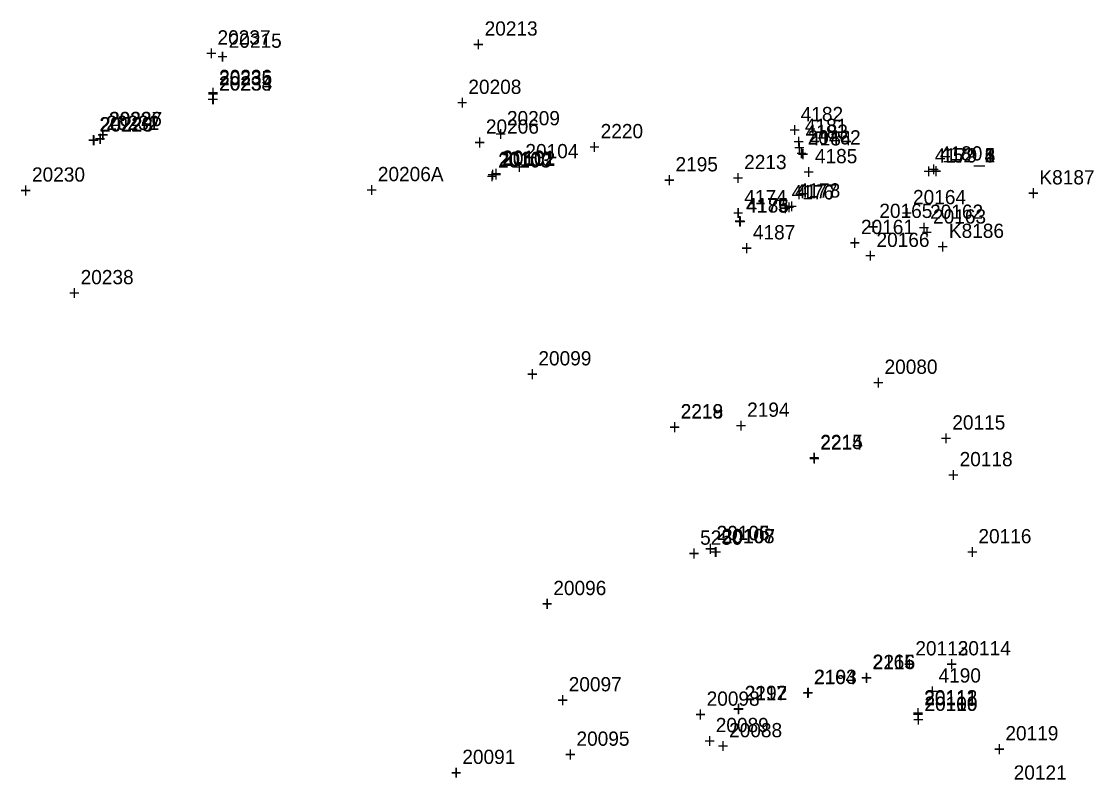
# Model space of a CAD drawing. Extents: x 1036751 to 1042192, y 772604 to 785439.
# Drawn here: x 1041373 to 1041558.5, y 774481.9 to 774615 of the extents above; entities that cross this region are included whole.
import ezdxf

# ---------------------------------------------------------------- set-up
doc = ezdxf.new("R2010")
doc.units = 0
for name, color, linetype in [('S_Annotation_Label', 7, 'Continuous'), ('S_Buildings', 7, 'Continuous'), ('S_Buildings_SillElevation', 7, 'Continuous'), ('S_Control_Temp_Traverse', 7, 'Continuous'), ('S_Curb_Type_2', 7, 'Continuous'), ('S_Drainage_CB', 7, 'Continuous'), ('S_Drainage_Culvert_Top', 7, 'Continuous'), ('S_Drainage_Invert', 7, 'Continuous'), ('S_Drainage_Sump', 7, 'Continuous'), ('S_Property_IronPipeFound', 7, 'Continuous'), ('S_Property_Lawn', 7, 'Continuous'), ('S_Roadway_Centerline', 7, 'Continuous'), ('S_Roadway_Edge_Pavement', 7, 'Continuous'), ('S_Roadway_Edge_TW', 7, 'Continuous'), ('S_Traffic_Sign_DoublePost', 7, 'Continuous'), ('S_Traffic_Sign_SinglePost', 7, 'Continuous'), ('S_Trees_Conifer_Pay', 7, 'Continuous'), ('S_Utilities_GuyWire3', 7, 'Continuous'), ('S_Utilities_Hydrant', 7, 'Continuous'), ('S_Utilities_Pole_Power', 7, 'Continuous'), ('S_Utilities_UG_Sanitary_MH', 7, 'Continuous'), ('S_Utilities_UG_Sanitary_Sewer', 7, 'Continuous'), ('S_Utilities_UG_Water_Gate', 7, 'Continuous'), ('S_Utilities_UG_Water_Line', 7, 'Continuous'), ('S_Utilities_UG_Water_Shutoff', 7, 'Continuous')]:
    doc.layers.add(name, color=color, linetype=linetype)

msp = doc.modelspace()

# ---------------------------------------------------------------- texts
at = {"layer": 'S_Annotation_Label'}
for s, p in [('20213', (1041454.27, 774612.43)), ('+', (1041452.21, 774609.68))]:
    msp.add_text(s, height=2.5, dxfattribs=at).set_placement(p)
at = {"layer": 'S_Buildings'}
for s, p in [('20206', (1041454.49, 774595.24)), ('+', (1041452.43, 774592.49)), ('20206A', (1041435.54, 774586.91)), ('+', (1041433.48, 774584.16)), ('20115', (1041536.3, 774543.36)), ('+', (1041534.23, 774540.61)), ('20116', (1041540.88, 774523.42)), ('+', (1041538.82, 774520.67)), ('20096', (1041466.32, 774514.34)), ('+', (1041464.26, 774511.59)), ('20119', (1041545.61, 774488.87)), ('20095', (1041470.38, 774487.92)), ('20091', (1041450.36, 774484.73)), ('+', (1041468.32, 774485.17)), ('+', (1041543.55, 774486.12)), ('+', (1041448.3, 774481.98))]:
    msp.add_text(s, height=2.5, dxfattribs=at).set_placement(p)
at = {"layer": 'S_Buildings_SillElevation'}
for s, p in [('20208', (1041451.42, 774602.21)), ('+', (1041449.36, 774599.46)), ('20118', (1041537.58, 774536.93)), ('+', (1041535.52, 774534.18)), ('20097', (1041469.02, 774497.46)), ('+', (1041466.96, 774494.71)), ('20121', (1041547.06, 774481.98))]:
    msp.add_text(s, height=2.5, dxfattribs=at).set_placement(p)
at = {"layer": 'S_Control_Temp_Traverse'}
for s, p in [('152', (1041534.53, 774590.2)), ('152', (1041534.53, 774590.2)), ('152_1', (1041534.53, 774590.2)), ('152_3', (1041534.53, 774590.2)), ('152_2', (1041534.53, 774590.2)), ('152_5', (1041534.53, 774590.2)), ('152_4', (1041534.53, 774590.2)), ('152_6', (1041534.53, 774590.2)), ('+', (1041532.47, 774587.45)), ('+', (1041532.47, 774587.45)), ('+', (1041532.47, 774587.45)), ('+', (1041532.47, 774587.45)), ('+', (1041532.47, 774587.45)), ('+', (1041532.47, 774587.45)), ('+', (1041532.47, 774587.45)), ('+', (1041532.47, 774587.45))]:
    msp.add_text(s, height=2.5, dxfattribs=at).set_placement(p)
at = {"layer": 'S_Curb_Type_2'}
for s, p in [('5250', (1041492.06, 774523.17)), ('+', (1041490, 774520.42))]:
    msp.add_text(s, height=2.5, dxfattribs=at).set_placement(p)
at = {"layer": 'S_Drainage_CB'}
for s, p in [('20234', (1041407.74, 774602.8)), ('+', (1041405.68, 774600.05)), ('20231', (1041387.9, 774595.9)), ('+', (1041385.84, 774593.15)), ('20103', (1041456.63, 774589.31)), ('+', (1041454.57, 774586.56)), ('20105', (1041494.96, 774524)), ('+', (1041492.9, 774521.25)), ('20109', (1041531.41, 774494.04)), ('+', (1041529.35, 774491.29))]:
    msp.add_text(s, height=2.5, dxfattribs=at).set_placement(p)
at = {"layer": 'S_Drainage_Culvert_Top'}
for s, p in [('20237', (1041407.42, 774610.87)), ('+', (1041405.35, 774608.12)), ('20236', (1041407.7, 774603.94)), ('+', (1041405.64, 774601.19)), ('20226', (1041388.35, 774596.56)), ('20229', (1041386.7, 774595.65)), ('+', (1041384.64, 774592.9)), ('+', (1041386.29, 774593.81)), ('20104', (1041461.42, 774590.93)), ('20102', (1041457.35, 774589.58)), ('20230', (1041374.88, 774586.83)), ('+', (1041459.36, 774588.18)), ('+', (1041455.29, 774586.83)), ('+', (1041372.81, 774584.08)), ('20108', (1041495.82, 774523.43)), ('+', (1041493.76, 774520.68)), ('20113', (1041529.82, 774503.76)), ('+', (1041527.76, 774501.01)), ('20112', (1041531.38, 774495.18)), ('+', (1041529.32, 774492.43))]:
    msp.add_text(s, height=2.5, dxfattribs=at).set_placement(p)
at = {"layer": 'S_Drainage_Invert'}
for s, p in [('20235', (1041407.7, 774603.73)), ('+', (1041405.64, 774600.98)), ('20227', (1041388.42, 774596.57)), ('20228', (1041386.81, 774595.61)), ('+', (1041384.75, 774592.86)), ('+', (1041386.35, 774593.82)), ('20101', (1041457.36, 774589.78)), ('+', (1041455.3, 774587.03)), ('20107', (1041495.92, 774523.42)), ('+', (1041493.86, 774520.67)), ('20111', (1041531.38, 774495.01)), ('+', (1041529.32, 774492.26))]:
    msp.add_text(s, height=2.5, dxfattribs=at).set_placement(p)
at = {"layer": 'S_Drainage_Sump'}
for s, p in [('20233', (1041407.67, 774602.8)), ('+', (1041405.61, 774600.05)), ('20232', (1041387.92, 774595.88)), ('+', (1041385.86, 774593.13)), ('20100', (1041456.76, 774589.58)), ('+', (1041454.7, 774586.83)), ('20106', (1041494.95, 774523.97)), ('+', (1041492.89, 774521.22)), ('20110', (1041531.43, 774494.04)), ('+', (1041529.37, 774491.29))]:
    msp.add_text(s, height=2.5, dxfattribs=at).set_placement(p)
at = {"layer": 'S_Property_IronPipeFound'}
for s, p in [('20215', (1041409.38, 774610.3)), ('+', (1041407.32, 774607.55)), ('20238', (1041383.41, 774568.84)), ('+', (1041381.35, 774566.09)), ('20080', (1041524.41, 774553.13)), ('+', (1041522.35, 774550.38)), ('20114', (1041537.25, 774503.77)), ('+', (1041535.19, 774501.02))]:
    msp.add_text(s, height=2.5, dxfattribs=at).set_placement(p)
at = {"layer": 'S_Property_Lawn'}
for s, p in [('K8187', (1041551.58, 774586.34)), ('+', (1041549.52, 774583.59)), ('K8186', (1041535.7, 774576.96)), ('+', (1041533.64, 774574.21))]:
    msp.add_text(s, height=2.5, dxfattribs=at).set_placement(p)
at = {"layer": 'S_Roadway_Centerline'}
for s, p in [('2195', (1041487.75, 774588.63)), ('+', (1041485.69, 774585.88)), ('2194', (1041500.31, 774545.6)), ('+', (1041498.25, 774542.85)), ('2164', (1041512.01, 774498.71)), ('2193', (1041512.1, 774498.76)), ('+', (1041509.95, 774495.96)), ('+', (1041510.04, 774496.01))]:
    msp.add_text(s, height=2.5, dxfattribs=at).set_placement(p)
at = {"layer": 'S_Roadway_Edge_Pavement'}
for s, p in [('2218', (1041488.67, 774545.29)), ('+', (1041486.61, 774542.54)), ('2215', (1041513.15, 774539.94)), ('+', (1041511.09, 774537.19)), ('2165', (1041522.29, 774501.4)), ('2216', (1041522.36, 774501.35)), ('+', (1041520.23, 774498.65)), ('+', (1041520.3, 774498.6)), ('2217', (1041499.87, 774495.89)), ('2192', (1041499.91, 774495.95)), ('+', (1041497.81, 774493.14)), ('+', (1041497.85, 774493.2))]:
    msp.add_text(s, height=2.5, dxfattribs=at).set_placement(p)
at = {"layer": 'S_Roadway_Edge_TW'}
for s, p in [('2220', (1041474.62, 774594.44)), ('+', (1041472.56, 774591.69)), ('2213', (1041499.79, 774589.02)), ('+', (1041497.73, 774586.27)), ('2219', (1041488.66, 774545.33)), ('+', (1041486.6, 774542.58)), ('2214', (1041513.16, 774539.83)), ('+', (1041511.1, 774537.08))]:
    msp.add_text(s, height=2.5, dxfattribs=at).set_placement(p)
at = {"layer": 'S_Traffic_Sign_DoublePost'}
for s, p in [('20164', (1041529.41, 774582.87)), ('20165', (1041523.5, 774580.46)), ('+', (1041527.35, 774580.12)), ('+', (1041521.44, 774577.71))]:
    msp.add_text(s, height=2.5, dxfattribs=at).set_placement(p)
at = {"layer": 'S_Traffic_Sign_SinglePost'}
for s, p in [('20209', (1041458.18, 774596.71)), ('+', (1041456.12, 774593.96)), ('20166', (1041523, 774575.38)), ('+', (1041520.94, 774572.63)), ('20098', (1041493.21, 774494.94)), ('+', (1041491.15, 774492.19))]:
    msp.add_text(s, height=2.5, dxfattribs=at).set_placement(p)
at = {"layer": 'S_Trees_Conifer_Pay'}
for s, p in [('20099', (1041463.7, 774554.61)), ('+', (1041461.64, 774551.86))]:
    msp.add_text(s, height=2.5, dxfattribs=at).set_placement(p)
at = {"layer": 'S_Utilities_GuyWire3'}
for s, p in [('20162', (1041532.4, 774580.31)), ('20163', (1041532.92, 774579.48)), ('+', (1041530.34, 774577.56)), ('+', (1041530.86, 774576.73))]:
    msp.add_text(s, height=2.5, dxfattribs=at).set_placement(p)
at = {"layer": 'S_Utilities_Hydrant'}
for s, p in [('4180', (1041534.13, 774590.53)), ('+', (1041532.07, 774587.78))]:
    msp.add_text(s, height=2.5, dxfattribs=at).set_placement(p)
at = {"layer": 'S_Utilities_Pole_Power'}
for s, p in [('20161', (1041520.28, 774577.64)), ('+', (1041518.22, 774574.89)), ('20089', (1041494.81, 774490.31)), ('20088', (1041497.15, 774489.41)), ('+', (1041492.75, 774487.56)), ('+', (1041495.09, 774486.66))]:
    msp.add_text(s, height=2.5, dxfattribs=at).set_placement(p)
at = {"layer": 'S_Utilities_UG_Sanitary_MH'}
for s, p in [('4183', (1041510.56, 774594.34)), ('+', (1041508.5, 774591.59))]:
    msp.add_text(s, height=2.5, dxfattribs=at).set_placement(p)
at = {"layer": 'S_Utilities_UG_Sanitary_Sewer'}
for s, p in [('4182', (1041509.71, 774597.43)), ('+', (1041507.65, 774594.68)), ('4181', (1041510.44, 774595.37)), ('+', (1041508.38, 774592.62)), ('20462', (1041510.93, 774593.34)), ('4184', (1041511.18, 774593.18)), ('+', (1041508.87, 774590.59)), ('+', (1041509.12, 774590.43)), ('4185', (1041512.2, 774590.06)), ('+', (1041510.14, 774587.31))]:
    msp.add_text(s, height=2.5, dxfattribs=at).set_placement(p)
at = {"layer": 'S_Utilities_UG_Water_Gate'}
for s, p in [('4177', (1041508.73, 774583.88)), ('+', (1041506.67, 774581.13))]:
    msp.add_text(s, height=2.5, dxfattribs=at).set_placement(p)
at = {"layer": 'S_Utilities_UG_Water_Line'}
for s, p in [('4179', (1041533.23, 774590.18)), ('+', (1041531.17, 774587.43)), ('4174', (1041499.82, 774582.87)), ('4176', (1041508.11, 774583.72)), ('4178', (1041509.21, 774584.04)), ('4175', (1041500.11, 774581.44)), ('4173', (1041500.13, 774581.39)), ('4186', (1041500.21, 774581.41)), ('+', (1041497.76, 774580.12)), ('+', (1041506.05, 774580.97)), ('+', (1041507.15, 774581.29)), ('+', (1041498.04, 774578.69)), ('+', (1041498.07, 774578.64)), ('+', (1041498.15, 774578.66)), ('4187', (1041501.32, 774576.7)), ('+', (1041499.26, 774573.95))]:
    msp.add_text(s, height=2.5, dxfattribs=at).set_placement(p)
at = {"layer": 'S_Utilities_UG_Water_Shutoff'}
for s, p in [('4190', (1041533.88, 774499)), ('+', (1041531.82, 774496.25))]:
    msp.add_text(s, height=2.5, dxfattribs=at).set_placement(p)

doc.saveas('drawing.dxf')
